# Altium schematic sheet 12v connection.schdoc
size 113 x 71 mm
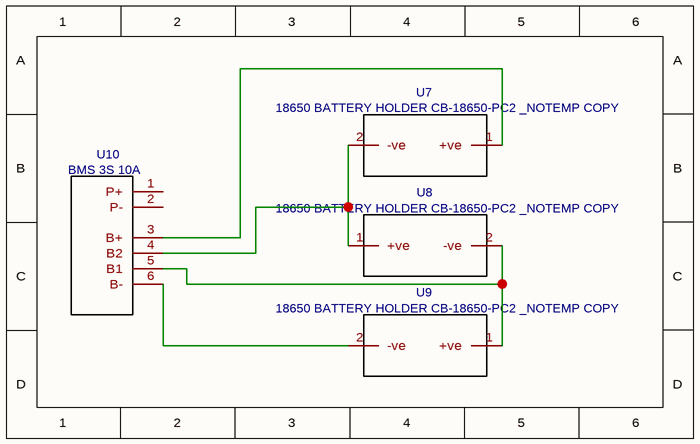
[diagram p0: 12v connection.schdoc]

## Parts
U7  18650 BATTERY HOLDER CB-18650-PC2 _NOTEMP COPY  [18650 BATTERY HOLDER CB-18650-PC2]
U8  18650 BATTERY HOLDER CB-18650-PC2 _NOTEMP COPY  [18650 BATTERY HOLDER CB-18650-PC2]
U9  18650 BATTERY HOLDER CB-18650-PC2 _NOTEMP COPY  [18650 BATTERY HOLDER CB-18650-PC2]
U10  BMS 3S 10A  [BMS 3S 10A]

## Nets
NetU7_1: U7.1(+ve) U10.3(B+)
NetU7_2: U7.2(-ve) U8.1(+ve) U10.4(B2)
NetU8_2: U8.2(-ve) U9.1(+ve) U10.5(B1)
NetU9_2: U9.2(-ve) U10.6(B-)

Not connected (* = marked no-connect by the designer): U10 1(P+) 2(P-)

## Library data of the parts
U7-U9 = 18650 BATTERY HOLDER CB-18650-PC2 _NOTEMP COPY: Contributor: recfvpernz
U10 = BMS 3S 10A: Contributor: annuarzainiabdullah68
